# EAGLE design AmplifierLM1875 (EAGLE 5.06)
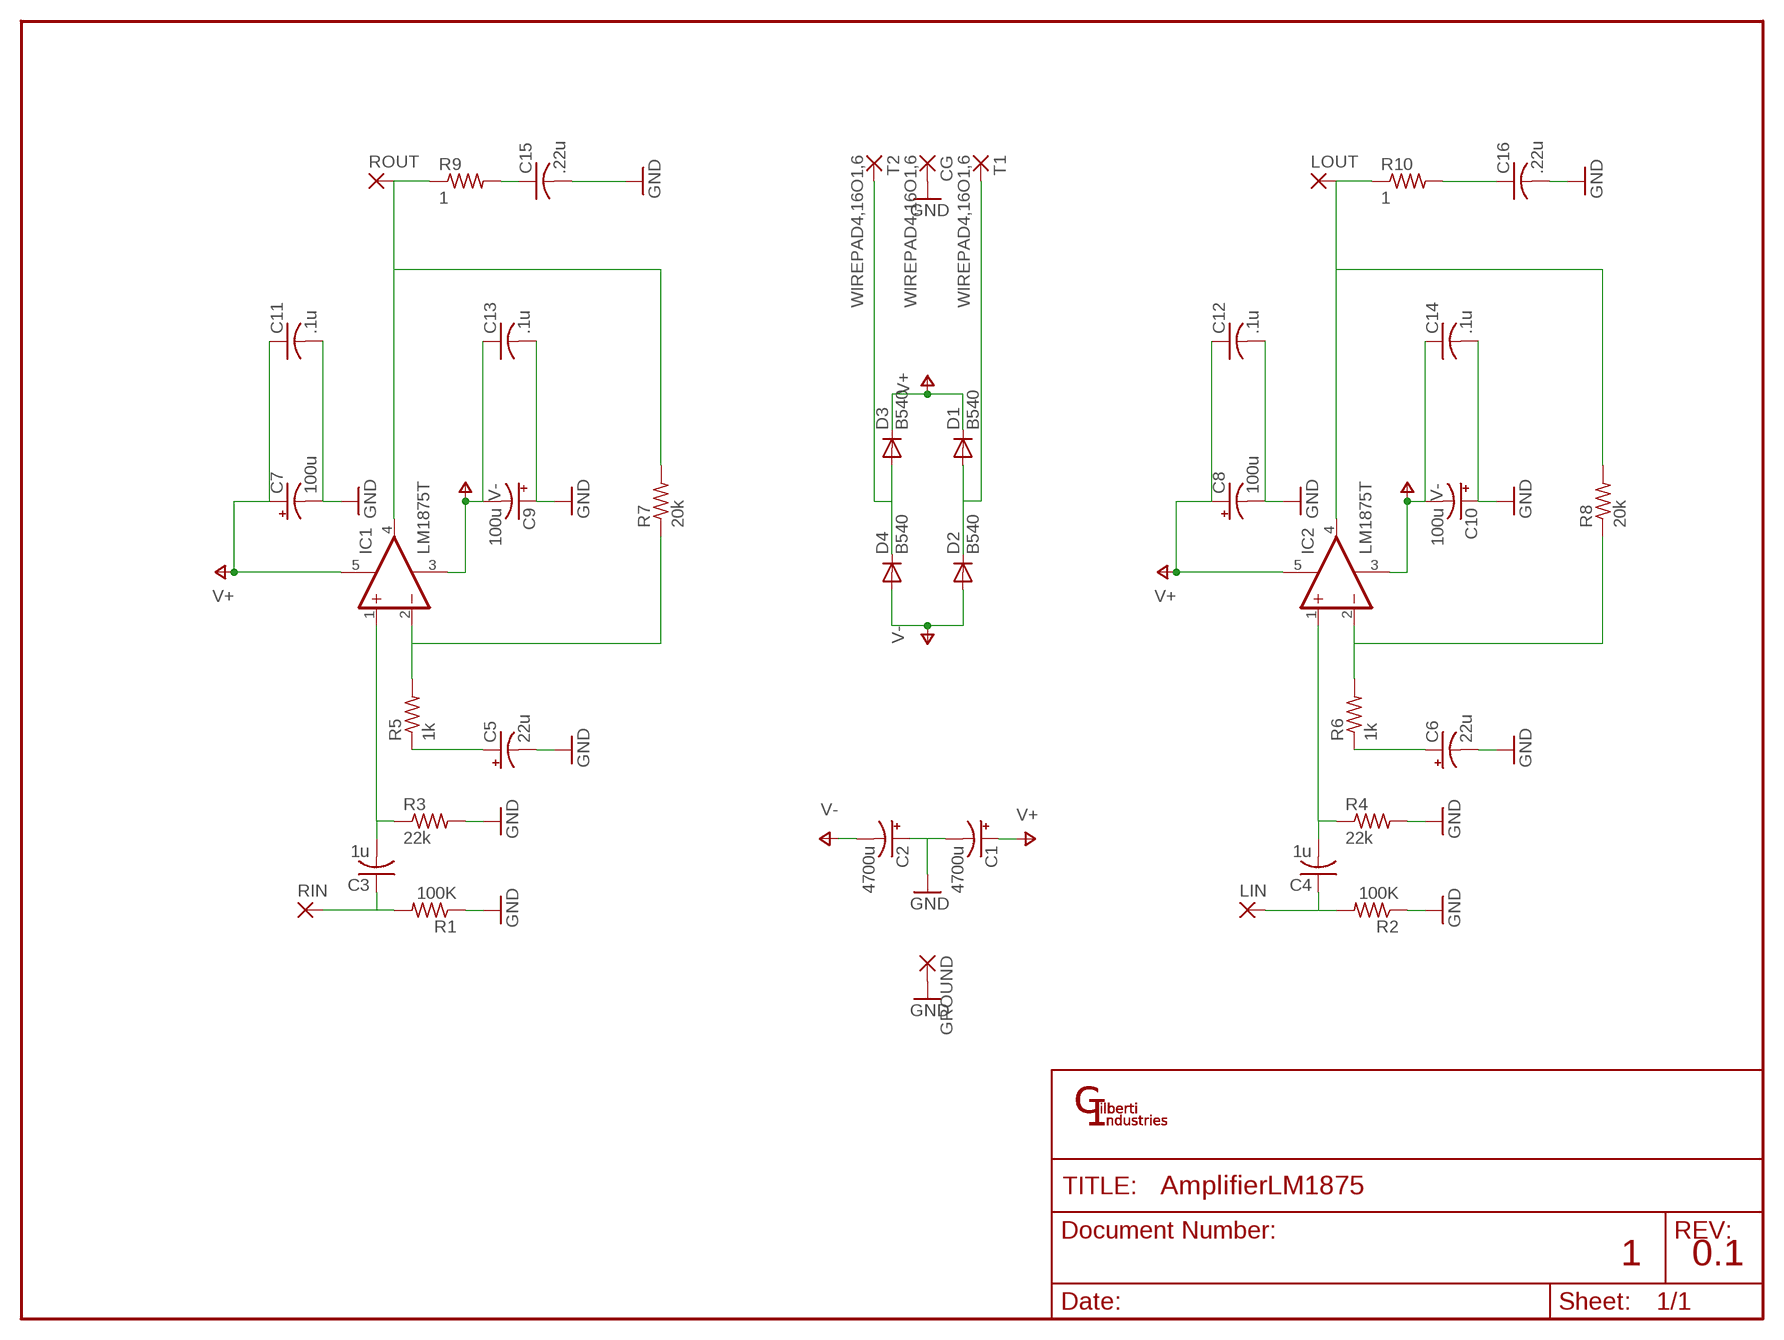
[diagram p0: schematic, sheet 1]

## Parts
C1  4700u  CPOL-USE7.5-18  [E7,5-18]
C2  4700u  CPOL-USE7.5-18  [E7,5-18]
C3  1u  C-US075-032X103  [C075-032X103]
C4  1u  C-US075-032X103  [C075-032X103]
C5  22u  CPOL-USE2-5  [E2-5]
C6  22u  CPOL-USE2-5  [E2-5]
C7  100u  CPOL-USE2.5-6  [E2,5-6]
C8  100u  CPOL-USE2.5-6  [E2,5-6]
C9  100u  CPOL-USE2.5-6  [E2,5-6]
C10  100u  CPOL-USE2.5-6  [E2,5-6]
C11  .1u  C-US050-025X075  [C050-025X075]
C12  .1u  C-US050-025X075  [C050-025X075]
C13  .1u  C-US050-025X075  [C050-025X075]
C14  .1u  C-US050-025X075  [C050-025X075]
C15  .22u  C-US050-025X075  [C050-025X075]
C16  .22u  C-US050-025X075  [C050-025X075]
CG  WIREPAD4,16O1,6  3,17/1,3  [3,17/1,3]
D1  B540  DIODE-DO201-15  [DO201-15]
D2  B540  DIODE-DO201-15  [DO201-15]
D3  B540  DIODE-DO201-15  [DO201-15]
D4  B540  DIODE-DO201-15  [DO201-15]
GROUND  1,6/0,8  [1,6/0,8]
IC1  LM1875T  [CB367]
IC2  LM1875T  [CB367]
LIN  1,6/0,8  [1,6/0,8]
LOUT  1,6/0,8  [1,6/0,8]
R1  100K  R-US_0207/2V  [0207/2V]
R2  100K  R-US_0207/2V  [0207/2V]
R3  22k  R-US_0207/2V  [0207/2V]
R4  22k  R-US_0207/2V  [0207/2V]
R5  1k  R-US_0207/2V  [0207/2V]
R6  1k  R-US_0207/2V  [0207/2V]
R7  20k  R-US_0207/2V  [0207/2V]
R8  20k  R-US_0207/2V  [0207/2V]
R9  1  R-US_0411/3V  [0411V]
R10  1  R-US_0411/3V  [0411V]
RIN  1,6/0,8  [1,6/0,8]
ROUT  1,6/0,8  [1,6/0,8]
T1  WIREPAD4,16O1,6  3,17/1,3  [3,17/1,3]
T2  WIREPAD4,16O1,6  3,17/1,3  [3,17/1,3]
U$1  FULLGILOGO  [LOGOCOMP]

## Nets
GND: C1.- C2.+ C5.- C6.- C7.- C8.- C9.+ C10.+ C11.2 C12.2 C13.2 C14.2 C15.2 C16.2 CG.1(P) GROUND.1(P) R1.1 R2.1 R3.2 R4.2
N$1: D3.A D4.C T2.1(P)
N$2: D1.A D2.C T1.1(P)
N$3: C3.1 R1.2 RIN.1(P)
N$4: C3.2 IC1.1(+IN) R3.1
N$5: C5.+ R5.1
N$6: IC1.2(-IN) R5.2 R7.1
N$7: C4.1 LIN.1(P) R2.2
N$8: C4.2 IC2.1(+IN) R4.1
N$9: C6.+ R6.1
N$10: IC2.2(-IN) R6.2 R8.1
N$11: IC1.4(OUT) R7.2 R9.1 ROUT.1(P)
N$12: C15.1 R9.2
N$13: IC2.4(OUT) LOUT.1(P) R8.2 R10.1
N$14: C16.1 R10.2
V+: C1.+ C7.+ C8.+ C11.1 C12.1 D1.C D3.C IC1.5(V+) IC2.5(V+)
V-: C2.- C9.- C10.- C13.1 C14.1 D2.A D4.A IC1.3(V-) IC2.3(V-)

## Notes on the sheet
- 1 | 0.1

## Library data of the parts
C1 C2 C5-C10 = rcl:CPOL-US: POLARIZED CAPACITOR, American symbol
C3 C4 C11-C16 = rcl:C-US: CAPACITOR, American symbol
CG T1 T2 = wirepad:3,17/1,3: THROUGH-HOLE PAD
D1-D4 = diode:DIODE-: DIODE
GROUND LIN LOUT RIN ROUT = wirepad:1,6/0,8: THROUGH-HOLE PAD
IC1 IC2 = linear:LM1875T: Power OP AMP
R1 R2 R5-R10 = rcl:R-US_: RESISTOR, American symbol
R3 R4 = resistor:R-US_: RESISTOR, American symbol
U$1 = GilbertiIndustries:FULLGILOGO

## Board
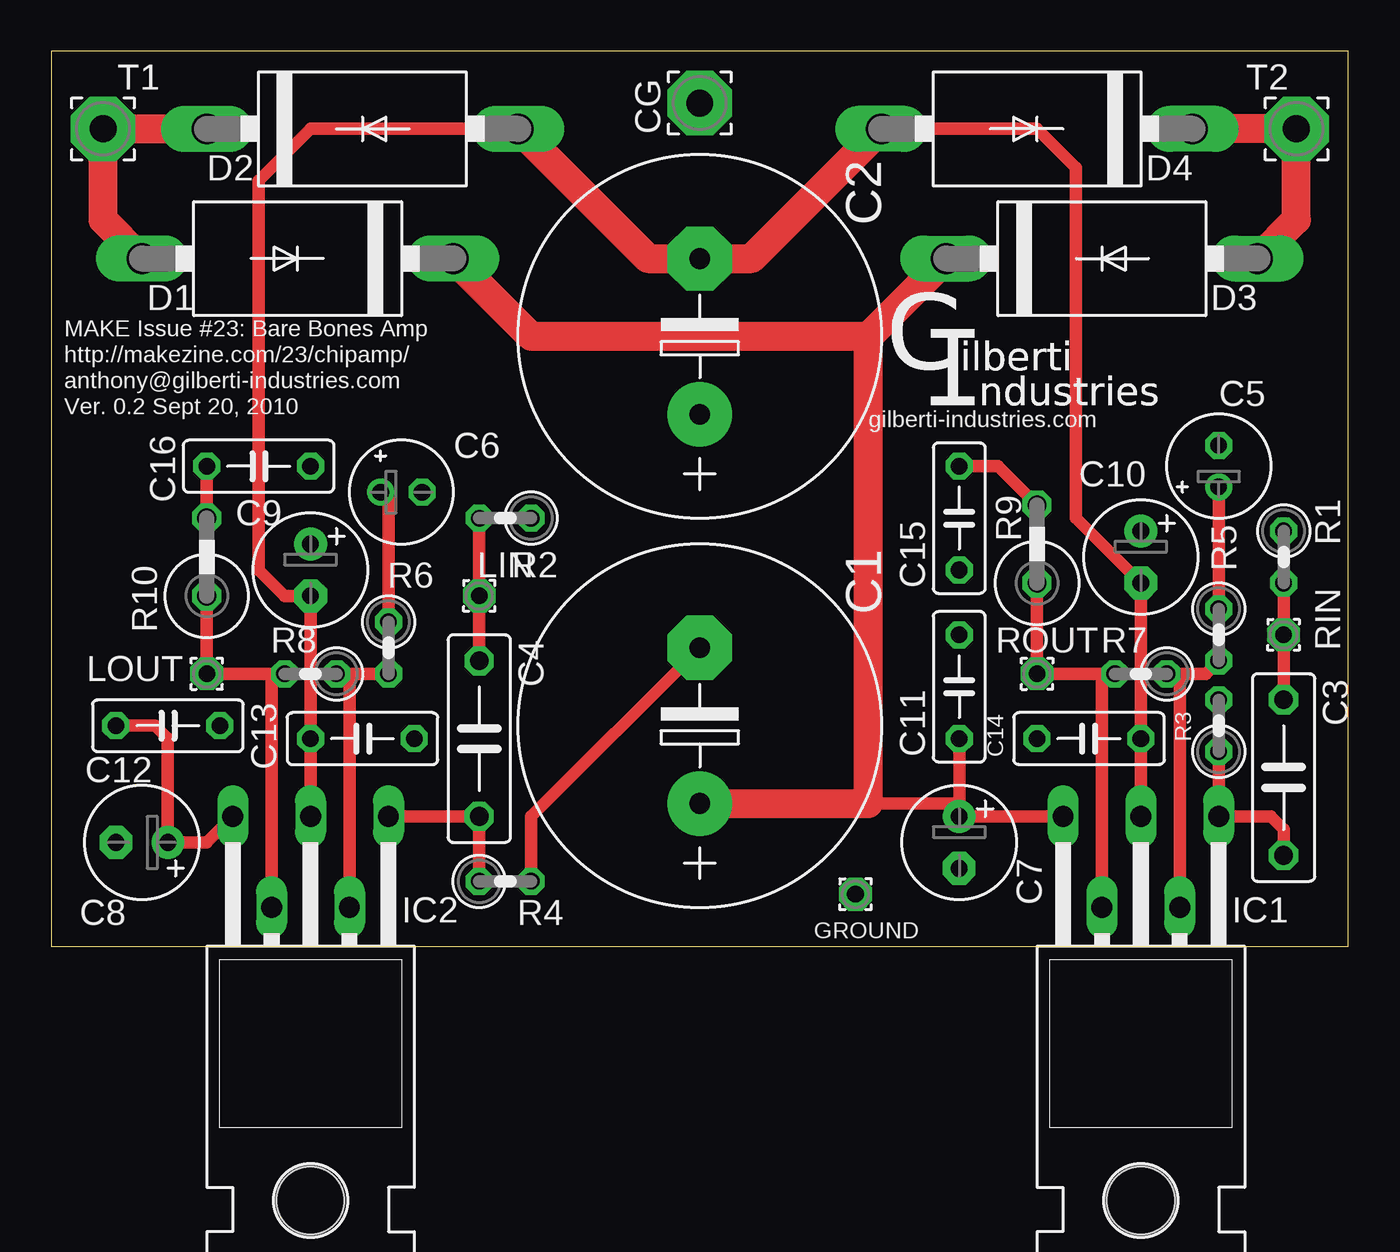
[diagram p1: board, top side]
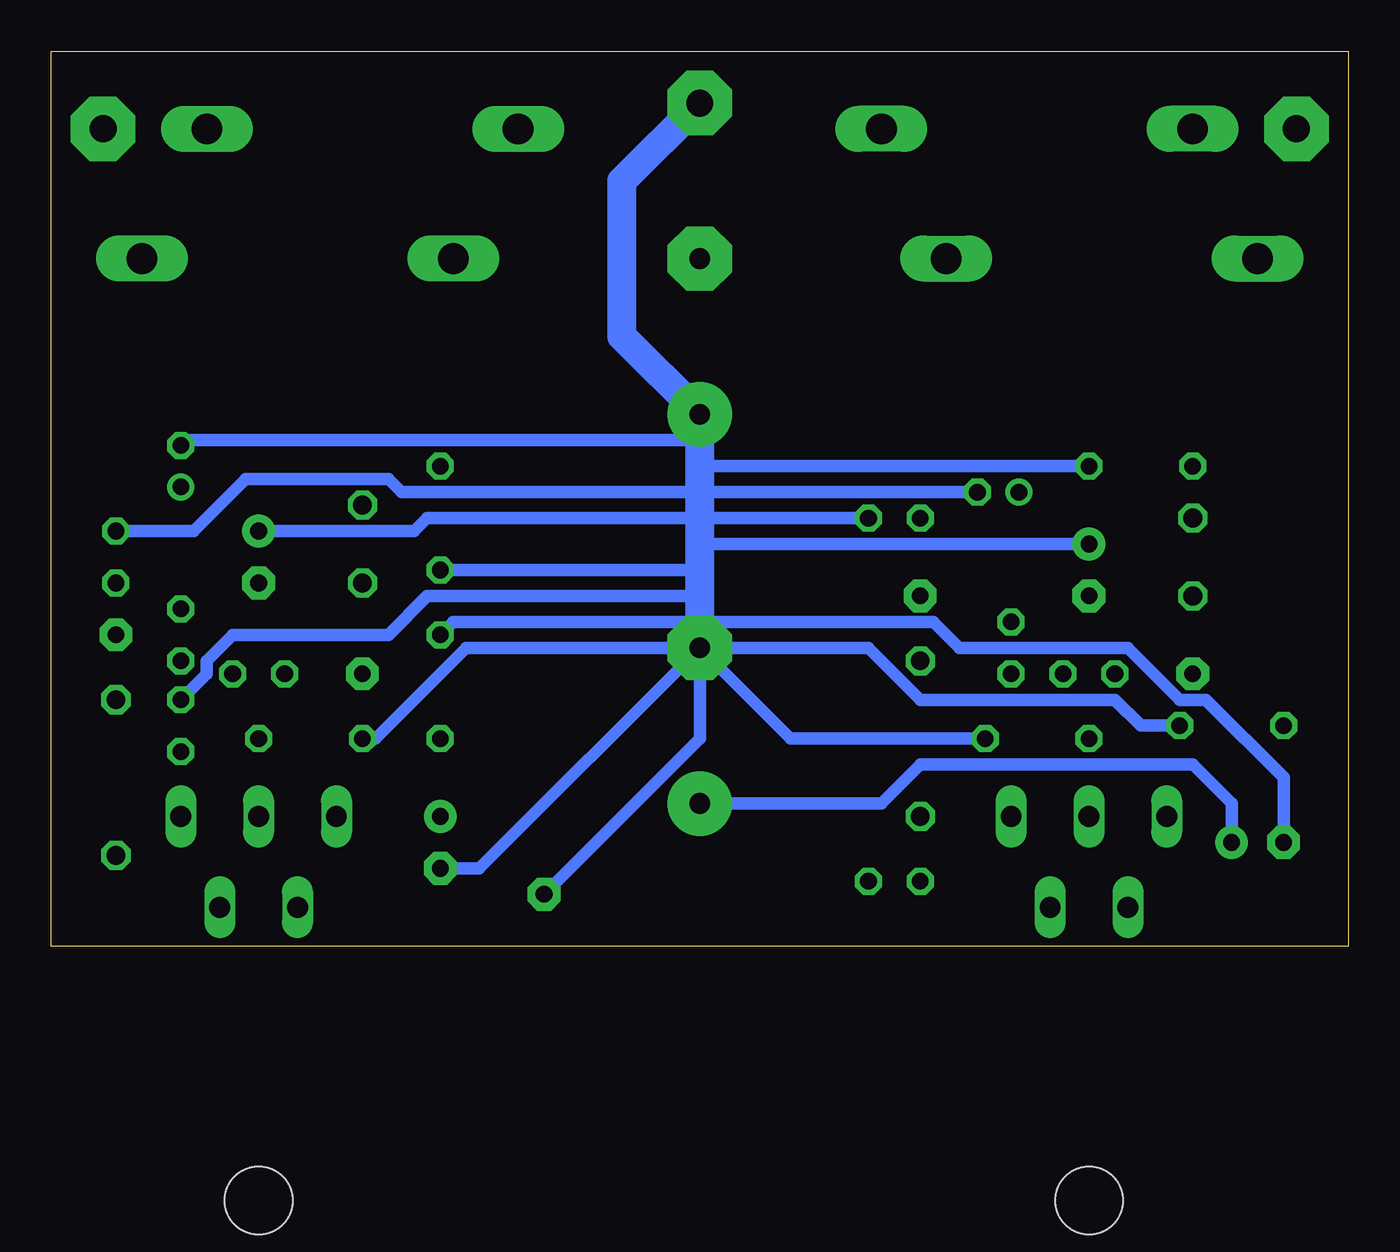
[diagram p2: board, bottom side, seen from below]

Size 63.5 x 43.81 mm. Coordinates in mm from the lower left corner, seen from the top.
Outline: 0,0 63.5,0 63.5,43.81 0,43.81 0,0
Copper layers (1*16): Top 0.035mm / dielectric 1.5mm / Bottom 0.035mm
Design rules "default": minimum track width 10mil, minimum drill 24mil, track to track 8mil, track to pad 8mil, pad to pad 8mil, via to via 8mil, smd to smd 8mil, copper to edge 40mil, drill to drill 8mil, minimum pad ring 10mil, minimum via ring 8mil, stop-mask expansion 4mil, vias tented up to drill 0mil, thermal gap 10mil

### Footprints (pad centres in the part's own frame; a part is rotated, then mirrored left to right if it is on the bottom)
E7,5-18 = drill 1.016 pad 3.15 round: + -3.81,0 | drill 1.016 pad 3.15 octagon: - 3.81,0
C075-032X103 = drill 0.914 octagon: 1 -3.81,0; 2 3.81,0
E2-5 = drill 0.813 pad 1.27 round: + -1.016,0 | drill 0.813 pad 1.27 octagon: - 1.016,0
E2,5-6 = drill 0.813 pad 1.6 round: + -1.27,0 | drill 0.813 pad 1.6 octagon: - 1.27,0
C050-025X075 = drill 0.813 octagon: 1 -2.54,0; 2 2.54,0
3,17/1,3 = drill 1.321 pad 3.175 octagon: 1 0,0
DO201-15 = drill 1.499 long: A 7.62,0; C -7.62,0
1,6/0,8 = drill 0.813 pad 1.6 octagon: 1 0,0
CB367 = drill 1.016 long: 1 -3.81,-11.43; 2 -1.905,-6.985; 3 0,-11.43; 4 1.905,-6.985; 5 3.81,-11.43 | hole 3.302: 0,7.366
0207/2V = drill 0.813 octagon: 1 -1.27,0; 2 1.27,0
0411V = drill 0.914 octagon: 1 -2.54,0; 2 1.27,0

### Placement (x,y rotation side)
C1  31.75,10.79 90 top
C2  31.75,29.84 90 top
C3  60.33,8.26 270 top
C4  20.95,10.16 270 top
C5  57.15,23.5 90 top
C6  17.14,22.23 0 top
C7  44.45,5.08 270 top
C8  4.45,5.08 180 top
C9  12.7,18.41 270 top
C10  53.34,19.05 270 top
C11  44.45,12.7 90 top
C12  5.71,10.79 0 top
C13  15.24,10.16 0 top
C14  50.8,10.16 180 top
C15  44.45,20.95 270 top
C16  10.16,23.5 0 top
CG  31.75,41.27 90 top
D1  12.06,33.66 180 top
D2  15.24,40.01 0 top
D3  51.44,33.66 0 top
D4  48.26,40.01 180 top
GROUND  39.37,2.54 0 top
IC1  53.34,-5.08 180 top
IC2  12.7,-5.08 180 top
LIN  20.95,17.14 0 top
LOUT  7.62,13.34 180 top
R1  60.33,19.05 270 top
R2  22.23,20.95 180 top
R3  57.15,10.79 90 top
R4  22.23,3.17 0 top
R5  57.15,15.24 270 top
R6  16.51,14.61 270 top
R7  53.34,13.34 180 top
R8  12.7,13.34 180 top
R9  48.26,20.32 90 top
R10  7.62,19.68 90 top
RIN  60.33,15.24 0 top
ROUT  48.26,13.34 180 top
T1  2.54,40.01 90 top
T2  60.96,40.01 90 top
U$1  47.62,29.21 0 top

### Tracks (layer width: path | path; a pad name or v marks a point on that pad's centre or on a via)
GND
  Top 0.61: R4.2 23.5,6.35 C1.-
  Bottom 0.61: C1.- 32.23,14.88 32.5,14.61 43.18,14.61 47.62,10.16 C14.2 | GROUND.1 31.75,10.16 C1.- | R2.1 31.75,20.95 45.09,20.95 45.72,20.32 C10.+ | 31.75,19.68 C9.+ | 31.75,18.41 C15.2 | C6.- 31.75,22.23 46.35,22.23 46.99,22.86 53.98,22.86 56.52,20.32 R1.1 | 31.75,23.5 C16.2 | 31.75,17.14 45.09,17.14 46.99,15.24 54.61,15.24 55.88,13.97 55.88,13.34 R3.2 | C11.2 43.81,15.88 31.75,15.88 20.32,15.88 19.05,14.61 10.79,14.61 8.26,12.06 6.99,12.06 3.17,8.26 C8.- | C7.- 42.55,3.81 C1.- | C5.- 57.15,24.77 31.75,24.77 | C12.2 10.16,10.79 11.43,12.06 20.95,12.06 23.5,14.61 C1.- | C13.2 27.3,10.16 C1.-
  Bottom 1.422: C1.- 31.75,15.88 31.75,17.14 31.75,18.41 31.75,19.68 31.75,20.95 31.75,22.23 31.75,23.5 31.75,24.77 C2.+ 35.56,29.84 35.56,37.47 CG.1
N$1
  Top 1.422: D4.C T2.1 60.96,35.56 D3.A
N$2
  Top 1.422: D2.C T1.1 2.54,35.56 D1.A
N$3
  Top 0.61: R1.2 RIN.1 C3.1
N$4
  Top 0.61: R3.1 IC1.1 59.69,6.35 60.33,5.71 C3.2
N$5
  Top 0.61: R5.1 C5.+
N$6
  Top 0.61: 55.24,13.34 R7.1 | IC1.2 55.24,13.34 | R5.2 56.52,13.34 55.24,13.34
N$7
  Top 0.61: R2.2 LIN.1 C4.1
N$8
  Top 0.61: IC2.1 C4.2 R4.1
N$9
  Top 0.61: R6.1 16.51,21.84 C6.+
N$10
  Top 0.61: 14.61,13.34 R8.1 | 14.61,13.34 R6.2 | IC2.2 14.61,13.34
N$11
  Top 0.61: 51.44,13.34 ROUT.1 R9.1 | 51.44,13.34 R7.2 | IC1.4 51.44,13.34
N$12
  Top 0.61: C15.1 46.35,23.5 R9.2
N$13
  Top 0.61: IC2.4 10.79,13.34 | 10.79,13.34 R8.2 | 10.79,13.34 LOUT.1 R10.1
N$14
  Top 0.61: R10.2 C16.1
V+
  Top 0.61: IC1.5 C7.+ 44.45,6.99 | 44.45,6.99 C11.1 | 40.01,6.99 44.45,6.99 | IC2.5 7.62,5.08 C8.+ 5.71,10.16 5.08,10.79 C12.1
  Top 1.422: D1.C 23.5,29.84 40.01,29.84 | 40.01,29.84 D3.C | C1.+ 40.01,6.99 40.01,29.84
  Bottom 0.61: C1.+ 22.86,6.99 20.95,8.89 7.62,8.89 5.71,6.99 C8.+
V-
  Top 0.61: IC1.3 C14.1 C10.- 50.16,20.95 50.16,38.1 48.26,40.01 D4.A | IC2.3 C13.1 C9.- 11.43,17.14 10.16,18.41 10.16,37.47 12.7,40.01 D2.A
  Top 1.422: D4.A 34.29,33.66 C2.- 29.21,33.66 D2.A

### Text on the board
tPlace: MAKE Issue #23: Bare Bones Amp | http://makezine.com/23/chipamp/ | anthony@gilberti-industries.com | Ver. 0.2 Sept 20, 2010 | gilberti-industries.com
